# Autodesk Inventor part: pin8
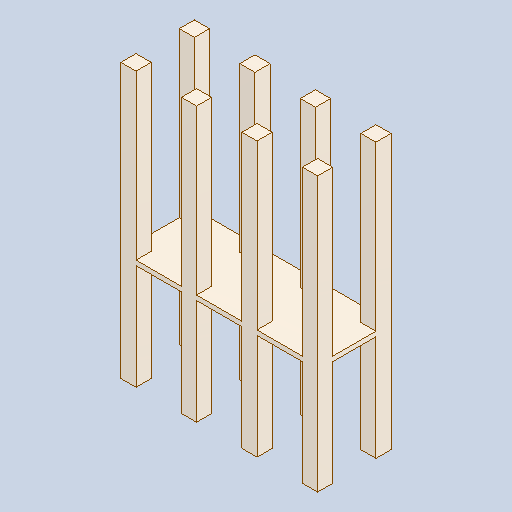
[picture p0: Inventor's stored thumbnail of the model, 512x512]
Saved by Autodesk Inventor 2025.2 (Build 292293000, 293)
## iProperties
Created: 2025-04
Part Number: pin8
Material: Generic
Description: PART--DESC
Document SubType Name: Modeling
Designer: BennF
Density: 1 g/cm^3
Appearance: Default
Author: BennF
Revision Number: NONE
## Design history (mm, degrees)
feature "Solid"
body "Solid1"
